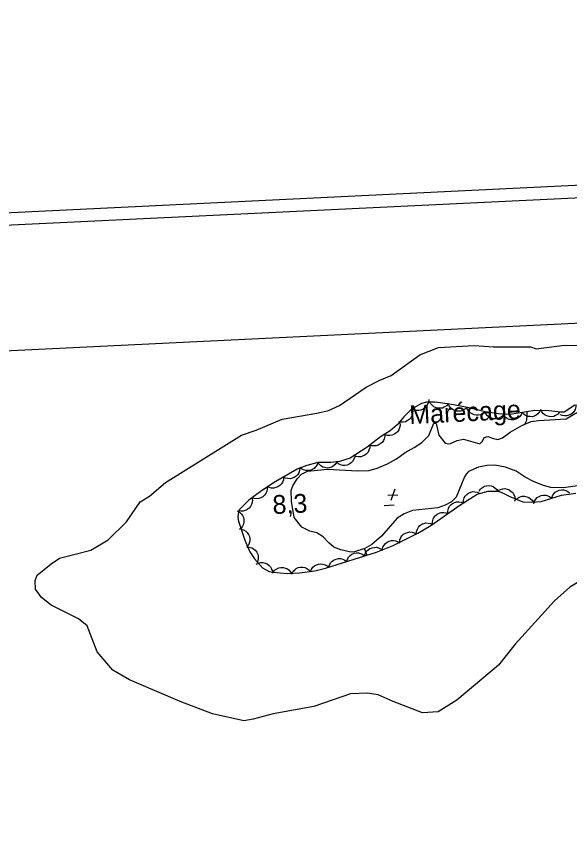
# Model space of a CAD drawing. Extents: x 336540 to 340074, y 5572036 to 5573747.
# Drawn here: x 336663.2 to 336751.6, y 5573486.7 to 5573616.8 of the extents above; entities that cross this region are included whole.
import ezdxf

# ---------------------------------------------------------------- set-up
doc = ezdxf.new("R2010")
doc.units = 0
for name, color, linetype in [('Niveau 2', 7, 'Continuous'), ('Niveau 3', 7, 'Continuous'), ('Niveau 4', 7, 'Continuous'), ('Niveau 44', 7, 'Continuous'), ('Niveau 60', 7, 'Continuous'), ('Niveau 7', 7, 'Continuous')]:
    doc.layers.add(name, color=color, linetype=linetype)

msp = doc.modelspace()

# ---------------------------------------------------------------- linework, layer by layer
at = {"layer": 'Niveau 2'}
msp.add_lwpolyline([(336754.39, 5573527.24), (336751.62, 5573525.57), (336749.17, 5573523.41), (336742.94, 5573516.48), (336740.24, 5573513.1), (336733.59, 5573507.51), (336730.64, 5573505.65), (336728.09, 5573505.51), (336723.43, 5573507.33), (336721.01, 5573508.39), (336719.31, 5573508.64), (336716.61, 5573508.51), (336710.78, 5573506.5), (336704.24, 5573505.31), (336701.07, 5573504.48), (336699.56, 5573504.23), (336694.59, 5573505.32), (336689.42, 5573507.28), (336681.29, 5573510.76), (336678.67, 5573512.3), (336676.15, 5573515.23), (336674.57, 5573519.39), (336673.17, 5573520.52), (336668.82, 5573522.69), (336667.24, 5573523.94), (336666.32, 5573525.26), (336666.26, 5573526.62), (336666.55, 5573527.48), (336668.82, 5573529.31), (336670.12, 5573530.21), (336675.12, 5573531.47), (336677.92, 5573533.14), (336680.82, 5573536.02), (336683.03, 5573539.19), (336684.51, 5573540.11), (336687.09, 5573542.29), (336699.22, 5573549.87), (336701.55, 5573550.65), (336705.7, 5573552.39), (336711.24, 5573553.36), (336713.09, 5573553.8), (336714.88, 5573554.57), (336719.14, 5573557.51), (336721.29, 5573558.62), (336723.1, 5573559.4), (336727.68, 5573562.69), (336730.68, 5573563.87), (336736.39, 5573564.17), (336739.46, 5573563.97), (336745.38, 5573563.95), (336746.25, 5573563.65), (336750.8, 5573564.22), (336756.89, 5573564.05)], dxfattribs=at)
at = {"layer": 'Niveau 3'}
for p, q in [((336723.69, 5573541.21), (336723.04, 5573539.41)), ((336722.6, 5573540.25), (336724.16, 5573540.33)), ((336721.98, 5573538.62), (336723.57, 5573538.7))]:
    msp.add_line(p, q, dxfattribs=at)
at = {"layer": 'Niveau 4'}
for points in [[(336707.62, 5573536.71), (336707.21, 5573539.29), (336707.16, 5573541), (336707.38, 5573541.77), (336708.09, 5573542.89), (336708.8, 5573543.6), (336709.77, 5573544.12), (336712.95, 5573544.42), (336717.71, 5573544.16), (336719.61, 5573544.23), (336720.88, 5573544.6), (336722.53, 5573545.29), (336723.94, 5573546.08), (336725.32, 5573547.09), (336726.79, 5573547.86), (336727.99, 5573548.69), (336729.15, 5573549.82), (336729.9, 5573551.79), (336730.27, 5573551.7), (336730.72, 5573549.87), (336731.73, 5573548.57), (336732.27, 5573548.46), (336732.59, 5573548.53), (336733.64, 5573549.01), (336734.67, 5573549.24), (336737.27, 5573548.47), (336737.68, 5573548.88), (336737.96, 5573549.47), (336738.56, 5573549.66), (336739.43, 5573549.33), (336740.14, 5573549.16), (336740.88, 5573549.45), (336742.09, 5573550.34), (336743.97, 5573551.41), (336745.49, 5573552.02), (336746.65, 5573552.19), (336751.05, 5573552.48), (336752.75, 5573553.49)], [(336755.06, 5573542.1), (336750.61, 5573541.46), (336748.59, 5573541.52), (336747.43, 5573541.83), (336745.95, 5573542.41), (336744.51, 5573543.15), (336743.07, 5573544.09), (336741.37, 5573544.77), (336739.66, 5573545.04), (336738.41, 5573545.02), (336737.06, 5573544.75), (336735.45, 5573544.03), (336735.08, 5573543.65), (336734.84, 5573543.19), (336733.49, 5573539.96), (336732.77, 5573539.22), (336731.75, 5573538.67), (336730.55, 5573538.26), (336726.52, 5573537.83), (336725.16, 5573537.27), (336724.05, 5573536.58), (336721.55, 5573533.7), (336720.02, 5573532.4), (336718.89, 5573531.74), (336717.25, 5573531.19), (336716.67, 5573531.17), (336715.05, 5573531.52), (336713.97, 5573531.98), (336713.14, 5573532.63), (336712.26, 5573533.62), (336711.25, 5573534.25), (336710.11, 5573534.54), (336708.83, 5573535.15), (336707.62, 5573536.71)]]:
    msp.add_lwpolyline(points, dxfattribs=at)
at = {"layer": 'Niveau 44'}
for points in [[(336752.43, 5573554.66), (336750.76, 5573553.55), (336750.19, 5573553.51), (336748.31, 5573553.73), (336746.03, 5573553.79), (336742.05, 5573553.14), (336740.27, 5573553.28), (336738.1, 5573553.57), (336735.28, 5573554.29), (336732.46, 5573554.82), (336730.16, 5573555.12), (336728.75, 5573555.11), (336727.98, 5573554.9), (336726.38, 5573553.99), (336725.15, 5573552.79), (336724.09, 5573551.49), (336722.94, 5573550.54), (336721.39, 5573549.59), (336719.26, 5573547.96), (336716.55, 5573546.17), (336714.88, 5573545.65), (336713.47, 5573545.5), (336711.39, 5573545.51), (336709.66, 5573545.02), (336708.12, 5573544.41), (336704.34, 5573542.24), (336702.18, 5573540.82), (336700.39, 5573539.45), (336698.85, 5573537.9), (336698.68, 5573537.31), (336698.64, 5573536.69), (336698.71, 5573536.12), (336699.72, 5573533.08), (336700.53, 5573531.21), (336701.28, 5573530.08), (336702.55, 5573528.67), (336703.61, 5573528.1), (336704.27, 5573527.95), (336706.52, 5573527.74), (336708.46, 5573527.85), (336710.92, 5573528.2), (336712.63, 5573528.6), (336720.79, 5573531.17), (336723.43, 5573532.22), (336727.38, 5573534.21), (336729.42, 5573535.42), (336734.06, 5573538.66), (336736.87, 5573540.41), (336738.58, 5573540.91), (336740.14, 5573540.89), (336740.76, 5573540.72), (336742.06, 5573540.07), (336744.13, 5573539.23), (336745.58, 5573539.15), (336747.07, 5573539.26), (336750.33, 5573540.25), (336752.63, 5573540.61)], [(336729.1, 5573555.54), (336729.07, 5573555.12), (336728.92, 5573554.74), (336728.76, 5573554.45), (336728.51, 5573554.21), (336728.2, 5573554), (336727.84, 5573553.87), (336727.53, 5573553.79), (336727.18, 5573553.81), (336726.82, 5573553.89), (336726.49, 5573554.05)], [(336732.22, 5573554.85), (336731.95, 5573554.54), (336731.6, 5573554.33), (336731.3, 5573554.19), (336730.95, 5573554.15), (336730.58, 5573554.16), (336730.21, 5573554.27), (336729.91, 5573554.4), (336729.65, 5573554.63), (336729.41, 5573554.92), (336729.25, 5573555.24)], [(336726.47, 5573554.08), (336726.55, 5573553.67), (336726.5, 5573553.27), (336726.42, 5573552.95), (336726.24, 5573552.64), (336726, 5573552.36), (336725.68, 5573552.15), (336725.39, 5573551.99), (336725.05, 5573551.92), (336724.68, 5573551.91), (336724.33, 5573551.99)], [(336735.17, 5573554.31), (336734.88, 5573554.01), (336734.52, 5573553.82), (336734.21, 5573553.7), (336733.86, 5573553.68), (336733.49, 5573553.71), (336733.13, 5573553.85), (336732.84, 5573553.99), (336732.59, 5573554.24), (336732.37, 5573554.53), (336732.22, 5573554.86)], [(336738.08, 5573553.57), (336737.77, 5573553.3), (336737.4, 5573553.13), (336737.08, 5573553.03), (336736.73, 5573553.03), (336736.37, 5573553.09), (336736.02, 5573553.24), (336735.73, 5573553.41), (336735.5, 5573553.67), (336735.3, 5573553.98), (336735.17, 5573554.32)], [(336746.99, 5573553.95), (336746.82, 5573553.57), (336746.54, 5573553.26), (336746.29, 5573553.05), (336745.97, 5573552.91), (336745.62, 5573552.81), (336745.23, 5573552.82), (336744.91, 5573552.85), (336744.59, 5573553), (336744.28, 5573553.2), (336744.03, 5573553.46)], [(336749.99, 5573553.53), (336749.72, 5573553.22), (336749.37, 5573553), (336749.07, 5573552.86), (336748.73, 5573552.81), (336748.36, 5573552.82), (336747.99, 5573552.93), (336747.69, 5573553.05), (336747.42, 5573553.28), (336747.18, 5573553.56), (336747.01, 5573553.88)], [(336752.62, 5573554.78), (336752.61, 5573554.37), (336752.49, 5573553.98), (336752.35, 5573553.68), (336752.12, 5573553.42), (336751.83, 5573553.18), (336751.48, 5573553.03), (336751.17, 5573552.93), (336750.82, 5573552.93), (336750.45, 5573552.99), (336750.12, 5573553.12)], [(336741.05, 5573553.18), (336740.78, 5573552.86), (336740.43, 5573552.65), (336740.13, 5573552.52), (336739.78, 5573552.47), (336739.41, 5573552.49), (336739.04, 5573552.6), (336738.74, 5573552.73), (336738.48, 5573552.96), (336738.24, 5573553.25), (336738.08, 5573553.57)], [(336744.03, 5573553.46), (336743.85, 5573553.08), (336743.58, 5573552.78), (336743.33, 5573552.57), (336743.01, 5573552.42), (336742.65, 5573552.33), (336742.27, 5573552.33), (336741.95, 5573552.37), (336741.63, 5573552.51), (336741.32, 5573552.72), (336741.07, 5573552.98)], [(336724.49, 5573551.82), (336724.53, 5573551.41), (336724.45, 5573551.01), (336724.35, 5573550.7), (336724.14, 5573550.41), (336723.88, 5573550.15), (336723.55, 5573549.96), (336723.25, 5573549.83), (336722.9, 5573549.79), (336722.53, 5573549.81), (336722.18, 5573549.91)], [(336722.05, 5573550.1), (336722.08, 5573549.68), (336721.98, 5573549.28), (336721.86, 5573548.98), (336721.65, 5573548.7), (336721.37, 5573548.45), (336721.04, 5573548.27), (336720.73, 5573548.15), (336720.38, 5573548.13), (336720.01, 5573548.16), (336719.67, 5573548.27)], [(336719.69, 5573548.24), (336719.69, 5573547.83), (336719.56, 5573547.44), (336719.42, 5573547.14), (336719.19, 5573546.88), (336718.9, 5573546.65), (336718.55, 5573546.49), (336718.24, 5573546.39), (336717.89, 5573546.39), (336717.52, 5573546.45), (336717.19, 5573546.59)], [(336717.28, 5573546.4), (336717.16, 5573546), (336716.93, 5573545.66), (336716.72, 5573545.41), (336716.42, 5573545.22), (336716.08, 5573545.08), (336715.7, 5573545.03), (336715.37, 5573545.02), (336715.03, 5573545.12), (336714.7, 5573545.28), (336714.42, 5573545.51)], [(336708.52, 5573544.64), (336708.49, 5573544.23), (336708.35, 5573543.85), (336708.19, 5573543.56), (336707.94, 5573543.31), (336707.63, 5573543.1), (336707.27, 5573542.97), (336706.96, 5573542.89), (336706.61, 5573542.91), (336706.25, 5573542.99), (336705.92, 5573543.15)], [(336711.4, 5573545.51), (336711.27, 5573545.12), (336711.04, 5573544.78), (336710.81, 5573544.54), (336710.51, 5573544.36), (336710.16, 5573544.23), (336709.78, 5573544.19), (336709.46, 5573544.19), (336709.12, 5573544.3), (336708.79, 5573544.46), (336708.51, 5573544.7)], [(336714.4, 5573545.5), (336714.17, 5573545.15), (336713.85, 5573544.9), (336713.57, 5573544.73), (336713.23, 5573544.64), (336712.86, 5573544.61), (336712.48, 5573544.67), (336712.17, 5573544.76), (336711.87, 5573544.96), (336711.6, 5573545.21), (336711.4, 5573545.51)], [(336705.92, 5573543.15), (336705.89, 5573542.73), (336705.75, 5573542.35), (336705.59, 5573542.06), (336705.34, 5573541.82), (336705.03, 5573541.6), (336704.67, 5573541.47), (336704.36, 5573541.39), (336704.01, 5573541.41), (336703.64, 5573541.5), (336703.32, 5573541.65)], [(336703.3, 5573541.68), (336703.32, 5573541.26), (336703.23, 5573540.86), (336703.11, 5573540.56), (336702.89, 5573540.28), (336702.62, 5573540.03), (336702.28, 5573539.85), (336701.98, 5573539.73), (336701.63, 5573539.7), (336701.26, 5573539.74), (336700.92, 5573539.85)], [(336734.63, 5573539.02), (336734.65, 5573539.43), (336734.78, 5573539.82), (336734.93, 5573540.11), (336735.17, 5573540.37), (336735.46, 5573540.59), (336735.82, 5573540.74), (336736.13, 5573540.83), (336736.48, 5573540.82), (336736.85, 5573540.75), (336737.18, 5573540.6)], [(336737.16, 5573540.93), (336737.4, 5573541.27), (336737.72, 5573541.52), (336738, 5573541.69), (336738.34, 5573541.78), (336738.71, 5573541.8), (336739.09, 5573541.74), (336739.4, 5573541.64), (336739.69, 5573541.45), (336739.96, 5573541.19), (336740.16, 5573540.89)], [(336740.2, 5573541), (336740.57, 5573541.2), (336740.96, 5573541.29), (336741.29, 5573541.32), (336741.64, 5573541.25), (336741.98, 5573541.11), (336742.29, 5573540.88), (336742.53, 5573540.67), (336742.71, 5573540.36), (336742.84, 5573540.01), (336742.89, 5573539.66)], [(336748.74, 5573539.77), (336748.86, 5573540.17), (336749.09, 5573540.5), (336749.31, 5573540.75), (336749.61, 5573540.93), (336749.95, 5573541.07), (336750.33, 5573541.12), (336750.66, 5573541.13), (336751, 5573541.03), (336751.33, 5573540.86), (336751.61, 5573540.64)], [(336700.86, 5573539.92), (336700.94, 5573539.51), (336700.9, 5573539.11), (336700.82, 5573538.79), (336700.64, 5573538.48), (336700.41, 5573538.2), (336700.1, 5573537.97), (336699.81, 5573537.81), (336699.47, 5573537.74), (336699.1, 5573537.73), (336698.74, 5573537.79)], [(336742.82, 5573539.3), (336743.07, 5573539.63), (336743.4, 5573539.87), (336743.7, 5573540.03), (336744.04, 5573540.1), (336744.41, 5573540.11), (336744.78, 5573540.03), (336745.09, 5573539.92), (336745.37, 5573539.71), (336745.63, 5573539.45), (336745.82, 5573539.14)], [(336745.87, 5573538.89), (336745.99, 5573539.29), (336746.22, 5573539.63), (336746.44, 5573539.88), (336746.74, 5573540.06), (336747.08, 5573540.2), (336747.46, 5573540.25), (336747.79, 5573540.26), (336748.12, 5573540.16), (336748.46, 5573539.99), (336748.74, 5573539.77)], [(336732.15, 5573537.33), (336732.15, 5573537.74), (336732.26, 5573538.14), (336732.39, 5573538.44), (336732.62, 5573538.71), (336732.9, 5573538.94), (336733.25, 5573539.11), (336733.56, 5573539.22), (336733.91, 5573539.22), (336734.27, 5573539.17), (336734.61, 5573539.04)], [(336698.51, 5573537.77), (336698.88, 5573537.58), (336699.17, 5573537.29), (336699.38, 5573537.03), (336699.51, 5573536.71), (336699.58, 5573536.35), (336699.57, 5573535.96), (336699.52, 5573535.64), (336699.36, 5573535.33), (336699.14, 5573535.02), (336698.87, 5573534.79)], [(336729.69, 5573535.61), (336729.69, 5573536.03), (336729.8, 5573536.42), (336729.93, 5573536.72), (336730.16, 5573536.99), (336730.44, 5573537.23), (336730.79, 5573537.39), (336731.1, 5573537.5), (336731.45, 5573537.51), (336731.82, 5573537.46), (336732.15, 5573537.33)], [(336727.12, 5573534.06), (336727.15, 5573534.48), (336727.29, 5573534.86), (336727.45, 5573535.15), (336727.69, 5573535.4), (336727.99, 5573535.61), (336728.35, 5573535.75), (336728.66, 5573535.84), (336729.02, 5573535.82), (336729.38, 5573535.74), (336729.71, 5573535.59)], [(336699.13, 5573534.85), (336699.54, 5573534.73), (336699.88, 5573534.51), (336700.13, 5573534.3), (336700.32, 5573534.01), (336700.47, 5573533.67), (336700.53, 5573533.29), (336700.54, 5573532.96), (336700.45, 5573532.62), (336700.3, 5573532.29), (336700.08, 5573532)], [(336724.44, 5573532.73), (336724.49, 5573533.14), (336724.66, 5573533.51), (336724.83, 5573533.79), (336725.09, 5573534.03), (336725.41, 5573534.22), (336725.77, 5573534.33), (336726.09, 5573534.4), (336726.44, 5573534.35), (336726.8, 5573534.25), (336727.11, 5573534.08)], [(336721.69, 5573531.53), (336721.78, 5573531.94), (336721.98, 5573532.29), (336722.18, 5573532.55), (336722.46, 5573532.76), (336722.79, 5573532.93), (336723.16, 5573533.01), (336723.49, 5573533.04), (336723.83, 5573532.97), (336724.18, 5573532.84), (336724.48, 5573532.64)], [(336700.03, 5573531.96), (336700.45, 5573531.96), (336700.84, 5573531.83), (336701.14, 5573531.69), (336701.4, 5573531.46), (336701.63, 5573531.17), (336701.79, 5573530.82), (336701.89, 5573530.51), (336701.89, 5573530.16), (336701.83, 5573529.79), (336701.69, 5573529.46)], [(336718.85, 5573530.56), (336718.97, 5573530.96), (336719.19, 5573531.3), (336719.41, 5573531.55), (336719.71, 5573531.74), (336720.05, 5573531.88), (336720.43, 5573531.93), (336720.76, 5573531.94), (336721.1, 5573531.84), (336721.43, 5573531.68), (336721.71, 5573531.46)], [(336715.99, 5573529.66), (336716.11, 5573530.06), (336716.33, 5573530.4), (336716.55, 5573530.65), (336716.85, 5573530.83), (336717.19, 5573530.98), (336717.57, 5573531.03), (336717.9, 5573531.04), (336718.23, 5573530.94), (336718.57, 5573530.78), (336718.85, 5573530.56)], [(336701.53, 5573529.22), (336701.9, 5573529.41), (336702.3, 5573529.49), (336702.63, 5573529.5), (336702.98, 5573529.42), (336703.31, 5573529.28), (336703.62, 5573529.04), (336703.85, 5573528.81), (336704.02, 5573528.5), (336704.14, 5573528.15), (336704.18, 5573527.8)], [(336710.22, 5573528.04), (336710.37, 5573528.43), (336710.62, 5573528.75), (336710.85, 5573528.98), (336711.16, 5573529.14), (336711.51, 5573529.26), (336711.9, 5573529.28), (336712.22, 5573529.27), (336712.55, 5573529.15), (336712.87, 5573528.96), (336713.14, 5573528.72)], [(336713.13, 5573528.76), (336713.25, 5573529.16), (336713.47, 5573529.5), (336713.69, 5573529.75), (336713.99, 5573529.93), (336714.33, 5573530.07), (336714.71, 5573530.13), (336715.03, 5573530.14), (336715.37, 5573530.04), (336715.71, 5573529.88), (336715.99, 5573529.66)], [(336704.24, 5573527.95), (336704.5, 5573528.28), (336704.84, 5573528.5), (336705.14, 5573528.65), (336705.48, 5573528.7), (336705.85, 5573528.7), (336706.22, 5573528.6), (336706.53, 5573528.49), (336706.8, 5573528.27), (336707.05, 5573527.99), (336707.22, 5573527.67)], [(336707.24, 5573527.68), (336707.42, 5573528.05), (336707.7, 5573528.35), (336707.95, 5573528.56), (336708.27, 5573528.7), (336708.63, 5573528.78), (336709.02, 5573528.77), (336709.34, 5573528.73), (336709.66, 5573528.58), (336709.96, 5573528.36), (336710.21, 5573528.1)]]:
    msp.add_lwpolyline(points, dxfattribs=at)
at = {"layer": 'Niveau 60'}
for points in [[(336614.31, 5572036.41), (340073.91, 5572203.88), (339999.21, 5573746.9), (336539.61, 5573579.43), (336614.31, 5572036.41)], [(336616.21, 5572038.51), (340071.82, 5572205.78), (339997.32, 5573744.81), (336541.71, 5573577.54), (336616.21, 5572038.51)], [(339458.94, 5573698.73), (339531.5, 5572199.65), (336635.22, 5572059.46), (336562.66, 5573558.54), (339458.94, 5573698.73)]]:
    msp.add_lwpolyline(points, dxfattribs=at)
at = {"layer": 'Niveau 7'}
for points in [[(336744.77, 5573553.59), (336744.8, 5573553.09), (336744.7, 5573552.21), (336744.4, 5573551.58)], [(336719.23, 5573530.74), (336718.87, 5573531.76)]]:
    msp.add_lwpolyline(points, dxfattribs=at)

# ---------------------------------------------------------------- texts
at = {"layer": 'Niveau 3'}
msp.add_text('    8,3 ', height=3, rotation=2.7712, dxfattribs=at).set_placement((336699.77, 5573537.03))
at = {"layer": 'Niveau 7'}
msp.add_text('Marécage', height=3, rotation=2.7781, dxfattribs=at).set_placement((336726.06, 5573551.61))

doc.saveas('drawing.dxf')
